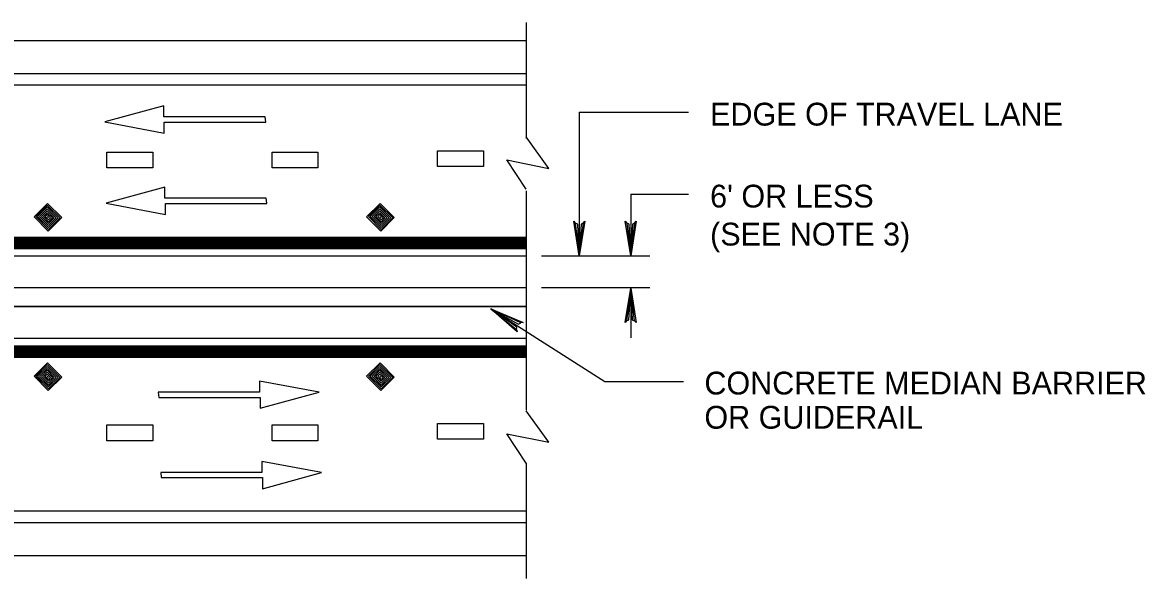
# Model space of a CAD drawing. Extents: x 639362 to 641108, y 298458 to 299646.
# Drawn here: x 639830.9 to 639978.6, y 299371.1 to 299444.2 of the extents above; entities that cross this region are included whole.
import ezdxf

# ---------------------------------------------------------------- set-up
doc = ezdxf.new("R2010")
doc.units = 0
doc.layers.add('2', color=7, linetype='Continuous')

msp = doc.modelspace()

# ---------------------------------------------------------------- linework, layer by layer
at = {"layer": '2'}
for p, q in [((639897.17, 299444.19), (639897.17, 299428.91)), ((639662.67, 299441.83), (639897.17, 299441.83)), ((639662.67, 299437.48), (639897.17, 299437.48)), ((639662.67, 299435.98), (639897.17, 299435.98)), ((639849.5, 299433.23), (639841.78, 299431.12)), ((639849.5, 299431.79), (639849.5, 299433.23)), ((639862.83, 299431.79), (639849.5, 299431.79)), ((639862.91, 299431.12), (639862.83, 299431.79)), ((639904.12, 299432.37), (639904.12, 299413.5)), ((639904.12, 299432.37), (639918.5, 299432.37)), ((639841.78, 299431.12), (639849.58, 299429.64)), ((639849.58, 299429.64), (639849.58, 299431.08)), ((639849.58, 299431.08), (639862.91, 299431.08)), ((639862.91, 299431.08), (639862.91, 299431.12)), ((639900.12, 299425), (639897.17, 299429.14)), ((639885.51, 299425.24), (639885.51, 299427.31)), ((639885.51, 299427.31), (639891.52, 299427.31)), ((639891.52, 299427.31), (639891.52, 299425.24)), ((639842.04, 299425.06), (639842.04, 299427.12)), ((639842.04, 299427.12), (639848.05, 299427.12)), ((639848.05, 299427.12), (639848.05, 299425.06)), ((639863.74, 299425.06), (639863.74, 299427.12)), ((639863.74, 299427.12), (639869.75, 299427.12)), ((639869.75, 299427.12), (639869.75, 299425.06)), ((639897.17, 299422.27), (639894.6, 299426.14)), ((639894.6, 299426.14), (639900.12, 299425)), ((639848.05, 299425.06), (639842.04, 299425.06)), ((639869.75, 299425.06), (639863.74, 299425.06)), ((639891.52, 299425.24), (639885.51, 299425.24)), ((639849.65, 299422.52), (639841.93, 299420.41)), ((639849.65, 299421.08), (639849.65, 299422.52)), ((639897.17, 299422.04), (639897.17, 299393.18)), ((639910.89, 299421.59), (639910.89, 299413.5)), ((639910.89, 299421.59), (639918.5, 299421.59)), ((639832.45, 299418.63), (639834.21, 299420.39)), ((639832.67, 299418.66), (639834.18, 299420.17)), ((639832.92, 299418.67), (639834.18, 299419.92)), ((639834.18, 299420.17), (639835.87, 299418.48)), ((639834.18, 299419.92), (639835.62, 299418.48)), ((639834.21, 299420.39), (639836.09, 299418.52)), ((639841.93, 299420.41), (639849.73, 299418.93)), ((639862.98, 299421.08), (639849.65, 299421.08)), ((639849.73, 299418.93), (639849.73, 299420.38)), ((639849.73, 299420.38), (639863.06, 299420.38)), ((639863.06, 299420.41), (639862.98, 299421.08)), ((639863.06, 299420.38), (639863.06, 299420.41)), ((639876.17, 299418.63), (639877.94, 299420.39)), ((639876.4, 299418.66), (639877.9, 299420.17)), ((639876.65, 299418.67), (639877.9, 299419.92)), ((639877.9, 299420.17), (639879.6, 299418.48)), ((639877.9, 299419.92), (639879.35, 299418.48)), ((639877.94, 299420.39), (639879.81, 299418.52)), ((639834.32, 299416.75), (639832.45, 299418.63)), ((639834.36, 299416.97), (639832.67, 299418.66)), ((639834.37, 299417.22), (639832.92, 299418.67)), ((639833.17, 299418.66), (639834.18, 299419.67)), ((639834.37, 299417.47), (639833.17, 299418.66)), ((639833.43, 299418.67), (639834.18, 299419.42)), ((639834.37, 299417.73), (639833.43, 299418.67)), ((639833.68, 299418.67), (639834.18, 299419.17)), ((639834.37, 299417.98), (639833.68, 299418.67)), ((639833.93, 299418.67), (639834.18, 299418.92)), ((639834.37, 299418.23), (639833.93, 299418.67)), ((639834.17, 299418.67), (639834.36, 299418.48)), ((639834.18, 299419.67), (639835.37, 299418.48)), ((639834.18, 299419.42), (639835.12, 299418.48)), ((639834.18, 299419.17), (639834.87, 299418.48)), ((639834.18, 299418.92), (639834.62, 299418.48)), ((639836.09, 299418.52), (639834.32, 299416.75)), ((639835.87, 299418.48), (639834.36, 299416.97)), ((639835.62, 299418.48), (639834.37, 299417.22)), ((639835.37, 299418.48), (639834.37, 299417.47)), ((639835.12, 299418.48), (639834.37, 299417.73)), ((639834.87, 299418.48), (639834.37, 299417.98)), ((639834.62, 299418.48), (639834.37, 299418.23)), ((639878.05, 299416.75), (639876.17, 299418.63)), ((639878.09, 299416.97), (639876.4, 299418.66)), ((639878.09, 299417.22), (639876.65, 299418.67)), ((639876.9, 299418.66), (639877.9, 299419.67)), ((639878.09, 299417.47), (639876.9, 299418.66)), ((639877.15, 299418.67), (639877.9, 299419.42)), ((639878.09, 299417.73), (639877.15, 299418.67)), ((639877.4, 299418.67), (639877.9, 299419.17)), ((639878.09, 299417.98), (639877.4, 299418.67)), ((639877.65, 299418.67), (639877.9, 299418.92)), ((639878.09, 299418.23), (639877.65, 299418.67)), ((639877.9, 299419.67), (639879.1, 299418.48)), ((639877.9, 299419.42), (639878.84, 299418.48)), ((639877.9, 299419.17), (639878.59, 299418.48)), ((639877.9, 299418.92), (639878.34, 299418.48)), ((639877.9, 299418.67), (639878.09, 299418.48)), ((639879.81, 299418.52), (639878.05, 299416.75)), ((639879.6, 299418.48), (639878.09, 299416.97)), ((639879.35, 299418.48), (639878.09, 299417.22)), ((639879.1, 299418.48), (639878.09, 299417.47)), ((639878.84, 299418.48), (639878.09, 299417.73)), ((639878.59, 299418.48), (639878.09, 299417.98)), ((639878.34, 299418.48), (639878.09, 299418.23)), ((639662.67, 299415.97), (639897.17, 299415.97)), ((639662.67, 299415.82), (639897.17, 299415.82)), ((639662.67, 299415.67), (639897.17, 299415.67)), ((639662.67, 299415.52), (639897.17, 299415.52)), ((639662.67, 299415.37), (639897.17, 299415.37)), ((639662.67, 299415.22), (639897.17, 299415.22)), ((639662.67, 299415.07), (639897.17, 299415.07)), ((639662.67, 299414.92), (639897.17, 299414.92)), ((639662.67, 299414.77), (639897.17, 299414.77)), ((639662.67, 299414.62), (639897.17, 299414.62)), ((639662.67, 299414.47), (639897.17, 299414.47)), ((639662.67, 299413.5), (639897.17, 299413.5)), ((639899.17, 299413.5), (639913.41, 299413.5)), ((639662.67, 299409.32), (639897.17, 299409.32)), ((639899.17, 299409.32), (639913.41, 299409.32)), ((639910.89, 299409.25), (639910.89, 299402.7)), ((639662.67, 299406.82), (639897.17, 299406.82)), ((639892.5, 299406.53), (639907.5, 299396.95)), ((639662.67, 299402.65), (639897.17, 299402.65)), ((639662.67, 299401.67), (639897.17, 299401.67)), ((639662.67, 299401.67), (639897.17, 299401.67)), ((639662.67, 299401.67), (639897.17, 299401.67)), ((639662.67, 299401.52), (639897.17, 299401.52)), ((639662.67, 299401.37), (639897.17, 299401.37)), ((639662.67, 299401.22), (639897.17, 299401.22)), ((639662.67, 299401.07), (639897.17, 299401.07)), ((639662.67, 299400.92), (639897.17, 299400.92)), ((639662.67, 299400.77), (639897.17, 299400.77)), ((639662.67, 299400.62), (639897.17, 299400.62)), ((639662.67, 299400.47), (639897.17, 299400.47)), ((639662.67, 299400.32), (639897.17, 299400.32)), ((639662.67, 299400.17), (639897.17, 299400.17)), ((639832.45, 299397.65), (639834.21, 299399.42)), ((639832.67, 299397.69), (639834.18, 299399.19)), ((639834.18, 299399.19), (639835.87, 299397.5)), ((639834.21, 299399.42), (639836.09, 299397.54)), ((639876.17, 299397.65), (639877.94, 299399.42)), ((639876.4, 299397.69), (639877.9, 299399.19)), ((639877.9, 299399.19), (639879.6, 299397.5)), ((639877.94, 299399.42), (639879.81, 299397.54)), ((639834.32, 299395.77), (639832.45, 299397.65)), ((639834.36, 299395.99), (639832.67, 299397.69)), ((639832.92, 299397.69), (639834.18, 299398.94)), ((639834.37, 299396.25), (639832.92, 299397.69)), ((639833.17, 299397.69), (639834.18, 299398.69)), ((639834.37, 299396.5), (639833.17, 299397.69)), ((639833.43, 299397.69), (639834.18, 299398.44)), ((639834.37, 299396.75), (639833.43, 299397.69)), ((639833.68, 299397.69), (639834.18, 299398.19)), ((639834.37, 299397), (639833.68, 299397.69)), ((639833.93, 299397.69), (639834.18, 299397.94)), ((639834.37, 299397.25), (639833.93, 299397.69)), ((639834.17, 299397.69), (639834.36, 299397.5)), ((639834.18, 299398.94), (639835.62, 299397.5)), ((639834.18, 299398.69), (639835.37, 299397.5)), ((639834.18, 299398.44), (639835.12, 299397.5)), ((639834.18, 299398.19), (639834.87, 299397.5)), ((639834.18, 299397.94), (639834.62, 299397.5)), ((639878.05, 299395.77), (639876.17, 299397.65)), ((639878.09, 299395.99), (639876.4, 299397.69)), ((639876.65, 299397.69), (639877.9, 299398.94)), ((639878.09, 299396.25), (639876.65, 299397.69)), ((639876.9, 299397.69), (639877.9, 299398.69)), ((639878.09, 299396.5), (639876.9, 299397.69)), ((639877.15, 299397.69), (639877.9, 299398.44)), ((639878.09, 299396.75), (639877.15, 299397.69)), ((639877.4, 299397.69), (639877.9, 299398.19)), ((639878.09, 299397), (639877.4, 299397.69)), ((639877.65, 299397.69), (639877.9, 299397.94)), ((639878.09, 299397.25), (639877.65, 299397.69)), ((639877.9, 299398.94), (639879.35, 299397.5)), ((639877.9, 299398.69), (639879.1, 299397.5)), ((639877.9, 299398.44), (639878.84, 299397.5)), ((639877.9, 299398.19), (639878.59, 299397.5)), ((639877.9, 299397.94), (639878.34, 299397.5)), ((639877.9, 299397.69), (639878.09, 299397.5)), ((639836.09, 299397.54), (639834.32, 299395.77)), ((639835.87, 299397.5), (639834.36, 299395.99)), ((639835.62, 299397.5), (639834.37, 299396.25)), ((639835.37, 299397.5), (639834.37, 299396.5)), ((639835.12, 299397.5), (639834.37, 299396.75)), ((639834.87, 299397.5), (639834.37, 299397)), ((639834.62, 299397.5), (639834.37, 299397.25)), ((639869.92, 299395.55), (639862.11, 299397.03)), ((639862.11, 299397.03), (639862.11, 299395.58)), ((639879.81, 299397.54), (639878.05, 299395.77)), ((639879.6, 299397.5), (639878.09, 299395.99)), ((639879.35, 299397.5), (639878.09, 299396.25)), ((639879.1, 299397.5), (639878.09, 299396.5)), ((639878.84, 299397.5), (639878.09, 299396.75)), ((639878.59, 299397.5), (639878.09, 299397)), ((639878.34, 299397.5), (639878.09, 299397.25)), ((639907.5, 299396.95), (639917.81, 299396.95)), ((639848.78, 299395.58), (639848.78, 299395.55)), ((639862.11, 299395.58), (639848.78, 299395.58)), ((639848.78, 299395.55), (639848.87, 299394.88)), ((639848.87, 299394.88), (639862.19, 299394.88)), ((639862.19, 299393.44), (639869.92, 299395.55)), ((639862.19, 299394.88), (639862.19, 299393.44)), ((639900.12, 299388.97), (639897.17, 299393.1)), ((639842.04, 299389.18), (639842.04, 299391.25)), ((639842.04, 299391.25), (639848.05, 299391.25)), ((639848.05, 299391.25), (639848.05, 299389.18)), ((639863.74, 299389.18), (639863.74, 299391.25)), ((639863.74, 299391.25), (639869.75, 299391.25)), ((639869.75, 299391.25), (639869.75, 299389.18)), ((639885.51, 299389.37), (639885.51, 299391.43)), ((639885.51, 299391.43), (639891.52, 299391.43)), ((639891.52, 299391.43), (639891.52, 299389.37)), ((639848.05, 299389.18), (639842.04, 299389.18)), ((639869.75, 299389.18), (639863.74, 299389.18)), ((639891.52, 299389.37), (639885.51, 299389.37)), ((639897.17, 299386.24), (639894.6, 299390.1)), ((639894.6, 299390.1), (639900.12, 299388.97)), ((639870.23, 299384.99), (639862.42, 299386.46)), ((639862.42, 299386.46), (639862.42, 299385.02)), ((639897.17, 299386.24), (639897.17, 299371.05)), ((639849.1, 299385.02), (639849.1, 299384.99)), ((639862.42, 299385.02), (639849.1, 299385.02)), ((639849.1, 299384.99), (639849.18, 299384.32)), ((639862.5, 299382.87), (639870.23, 299384.99)), ((639849.18, 299384.32), (639862.5, 299384.32)), ((639862.5, 299384.32), (639862.5, 299382.87)), ((639662.67, 299379.94), (639897.17, 299379.94)), ((639662.67, 299378.44), (639897.17, 299378.44)), ((639662.67, 299374.09), (639897.17, 299374.09))]:
    msp.add_line(p, q, dxfattribs=at)
for points in [[(639904.67, 299417.82), (639904.36, 299417.66), (639904.12, 299413.5), (639904.67, 299417.82), (639904.86, 299418.04), (639904.12, 299413.5), (639903.92, 299417.65), (639903.61, 299417.8), (639904.12, 299413.5), (639903.41, 299418.04), (639903.61, 299417.8)], [(639911.43, 299417.82), (639911.12, 299417.66), (639910.89, 299413.5), (639911.43, 299417.82), (639911.62, 299418.04), (639910.89, 299413.5), (639910.68, 299417.65), (639910.37, 299417.8), (639910.89, 299413.5), (639910.17, 299418.04), (639910.37, 299417.8)], [(639910.35, 299404.93), (639910.66, 299405.09), (639910.89, 299409.25), (639910.35, 299404.93), (639910.15, 299404.71), (639910.89, 299409.25), (639911.09, 299405.1), (639911.4, 299404.94), (639910.89, 299409.25), (639911.61, 299404.71), (639911.4, 299404.94)], [(639895.88, 299403.79), (639895.91, 299404.13), (639892.5, 299406.53), (639895.88, 299403.79), (639895.97, 299403.5), (639892.5, 299406.53), (639896.14, 299404.51), (639896.43, 299404.69), (639892.5, 299406.53), (639896.74, 299404.74), (639896.43, 299404.69)]]:
    msp.add_lwpolyline(points, dxfattribs=at)
msp.add_lwpolyline([(639662.67, 299409.32), (639897.17, 299409.32), (639897.17, 299406.82), (639662.67, 299406.82)], close=True, dxfattribs=at)

# ---------------------------------------------------------------- texts
for s, p in [('EDGE OF TRAVEL LANE', (639921.33, 299430.63)), ("6' OR LESS", (639921.33, 299419.85)), ('(SEE NOTE 3)', (639921.33, 299414.85)), ('CONCRETE MEDIAN BARRIER', (639920.58, 299395.26)), ('OR GUIDERAIL', (639920.58, 299390.76))]:
    msp.add_text(s, height=3, dxfattribs=at).set_placement(p)

doc.saveas('drawing.dxf')
